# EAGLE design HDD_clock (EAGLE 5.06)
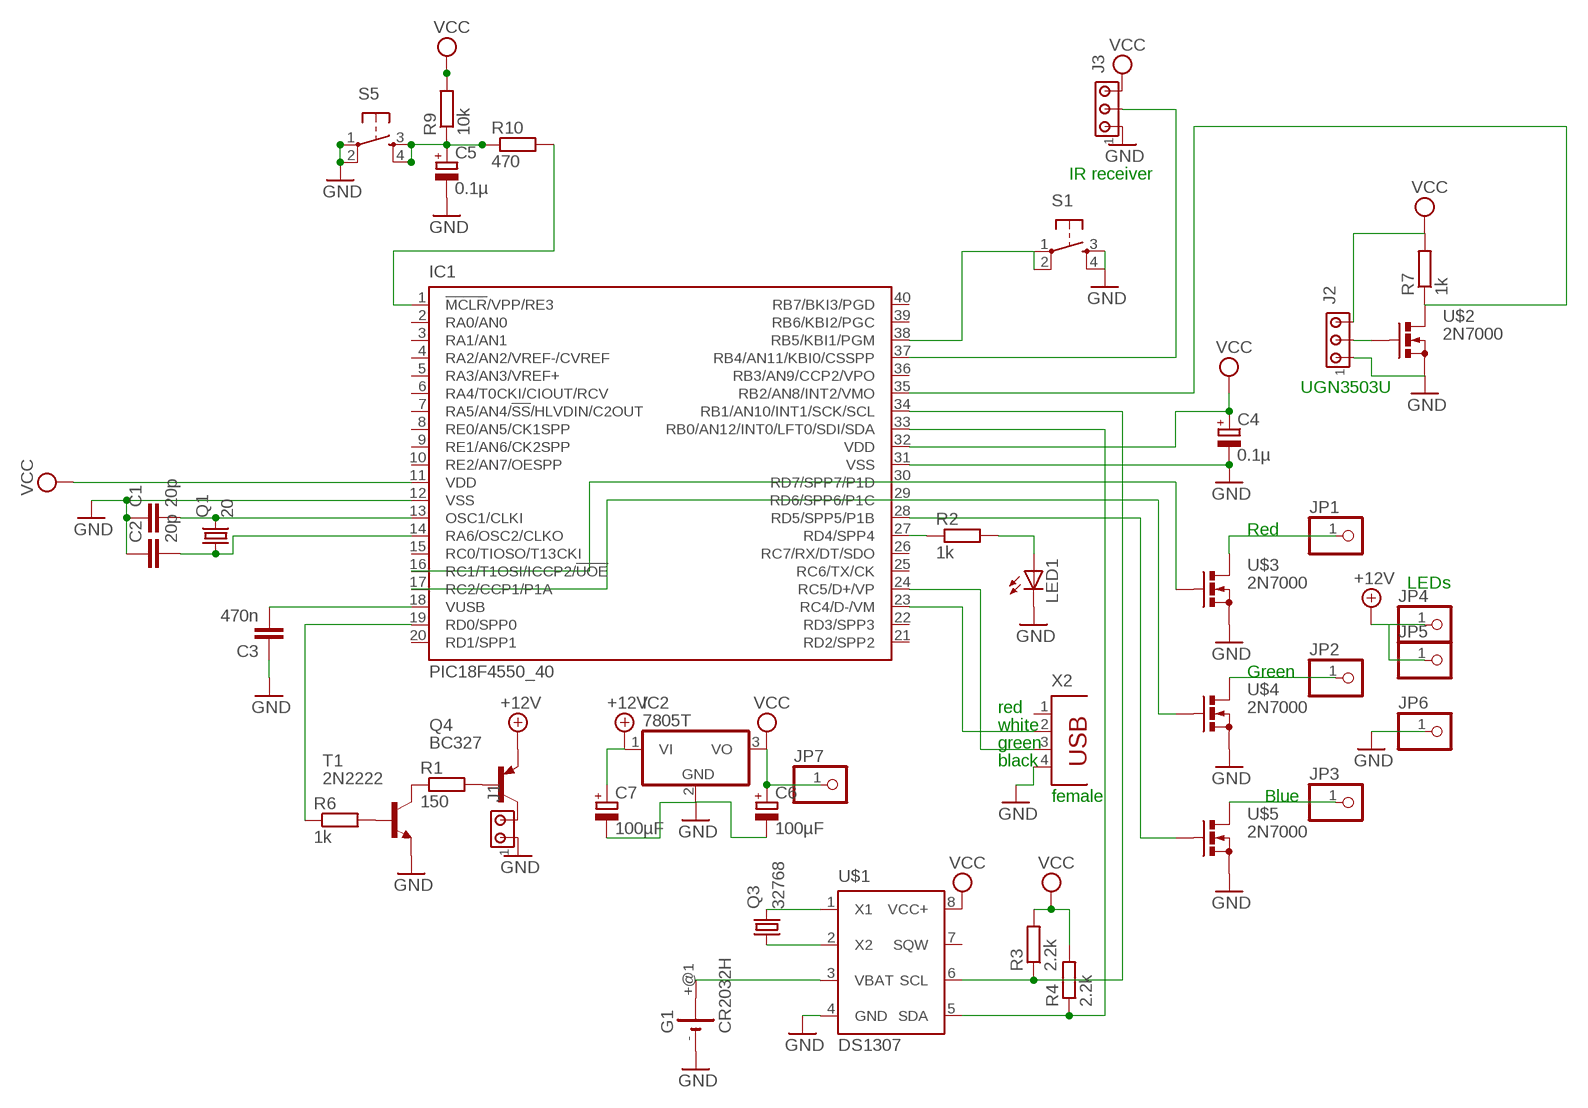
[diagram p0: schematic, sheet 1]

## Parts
C1  20p  C2.5/2  [C2.5-2]
C2  20p  C2.5/2  [C2.5-2]
C3  470n  C2.5/2  [C2.5-2]
C4  0.1µ  CPOL-EUE3.5-8  [E3,5-8]
C5  0.1µ  CPOL-EUE3.5-8  [E3,5-8]
C6  100µF  CPOL-EUTT5D7L  [TT5D7L]
C7  100µF  CPOL-EUTT5D7L  [TT5D7L]
G1  CR2032H  [CR2032H]
IC1  PIC18F4550_40  [DIL40]
IC2  7805T  [TO220H]
J1  MTA02-100  [10X02MTA]
J2  MTA03-100  [10X03MTA]
J3  MTA03-100  [10X03MTA]
JP1  PINHD-1X1  [1X01]
JP2  PINHD-1X1  [1X01]
JP3  PINHD-1X1  [1X01]
JP4  PINHD-1X1  [1X01]
JP5  PINHD-1X1  [1X01]
JP6  PINHD-1X1  [1X01]
JP7  PINHD-1X1  [1X01]
LED1  LED3MM  [LED3MM]
Q1  20  CRYSTALHC49S  [HC49/S]
Q3  32768  CRYSTALTC38H  [TC38H]
Q4  BC327  [TO92-EBC]
R1  150  R-EU_0207/15  [0207/15]
R2  1k  R-EU_0204/7  [0204/7]
R3  2.2k  R-EU_0204/7  [0204/7]
R4  2.2k  R-EU_0204/7  [0204/7]
R6  1k  R-EU_0204/7  [0204/7]
R7  1k  R-EU_0204/7  [0204/7]
R9  10k  R-EU_0204/7  [0204/7]
R10  470  R-EU_0204/7  [0204/7]
S1  TAC_SWITCHPTH  [TACTILE-PTH]
S5  TAC_SWITCHPTH  [TACTILE-PTH]
T1  2N2222  [TO18]
U$1  DS1307  [DIL8]
U$2  2N7000  [TO-92-SGD]
U$3  2N7000  [TO-92-SGD]
U$4  2N7000  [TO-92-SGD]
U$5  2N7000  [TO-92-SGD]
X2  PN87520  [PN87520]

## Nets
+12V: C7.+ IC2.1(VI) JP4.1 JP5.1 Q4.E
GND: LED1.K(C)
N$1: IC1.24(RC5/D+/VP) X2.3
N$2: C5.+ R9.1 R10.1 S5.3 S5.4
N$3: Q4.B R1.2
N$4: IC1.19(RD0/SPP0) R6.1
N$5: IC1.1(!MCLR!/VPP/RE3) R10.2
N$6: C1.2 IC1.13(OSC1/CLKI) Q1.2
N$7: C2.2 IC1.14(RA6/OSC2/CLKO) Q1.1
N$8: J1.2 Q4.C
N$9: C3.2 IC1.18(VUSB)
N$10: IC1.37(RB4/AN11/KBI0/CSSPP) J3.2
N$11: J2.2 U$2.G
N$13: C1.1 C2.1 C3.1 C4.- C5.- C6.- C7.- G1.- IC1.12(VSS) IC1.31(VSS) IC2.2(GND) J1.1 J2.1 J3.1 JP6.1 S1.3 S1.4 S5.1 S5.2 T1.1(E) U$1.4(GND) U$2.S U$3.S U$4.S U$5.S X2.4 ; supply symbol labelled GND
N$14: JP2.1 U$4.D
N$15: JP3.1 U$5.D
N$16: JP1.1 U$3.D
N$17: IC1.16(RC1/T1OSI/ICCP2/!UOE) U$3.G
N$18: IC1.17(RC2/CCP1/P1A) U$4.G
N$19: IC1.28(RD5/SPP5/P1B) U$5.G
N$20: Q3.2 U$1.1(X1)
N$21: Q3.1 U$1.2(X2)
N$22: G1.+@1(+) U$1.3(VBAT)
N$23: IC1.33(RB0/AN12/INT0/LFT0/SDI/SDA) R4.1 U$1.5(SDA)
N$24: IC1.38(RB5/KBI1/PGM) S1.1 S1.2
N$25: IC1.34(RB1/AN10/INT1/SCK/SCL) R3.1 U$1.6(SCL)
N$26: R1.1 T1.3(C)
N$27: R6.2 T1.2(B)
N$29: IC1.35(RB2/AN8/INT2/VMO) R7.1 U$2.D
N$44: IC1.27(RD4/SPP4) R2.1
N$45: LED1.A R2.2
N$70: IC1.23(RC4/D-/VM) X2.2
VCC: C4.+ C6.+ IC1.11(VDD) IC1.32(VDD) IC2.3(VO) J2.3 J3.3 JP7.1 R3.2 R4.2 R7.2 R9.2 U$1.8(VCC+)
Unconnected: G1.+ IC1.2(RA0/AN0) IC1.3(RA1/AN1) IC1.4(RA2/AN2/VREF-/CVREF) IC1.5(RA3/AN3/VREF+) IC1.6(RA4/T0CKI/CIOUT/RCV) IC1.7(RA5/AN4/!SS!/HLVDIN/C2OUT) IC1.8(RE0/AN5/CK1SPP) IC1.9(RE1/AN6/CK2SPP) IC1.10(RE2/AN7/OESPP) IC1.15(RC0/TIOSO/T13CKI) IC1.20(RD1/SPP1) IC1.21(RD2/SPP2) IC1.22(RD3/SPP3) IC1.25(RC6/TX/CK) IC1.26(RC7/RX/DT/SDO) IC1.29(RD6/SPP6/P1C) IC1.30(RD7/SPP7/P1D) IC1.36(RB3/AN9/CCP2/VPO) IC1.39(RB6/KBI2/PGC) IC1.40(RB7/BKI3/PGD) U$1.7(SQW) X2.1

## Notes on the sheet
- IR receiver
- UGN3503U
- Red
- LEDs
- Green
- red
- white
- green
- black
- female | Blue

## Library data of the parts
C1-C3 = capacitor-wima:C: CAPACITOR
C4-C7 = rcl:CPOL-EU: POLARIZED CAPACITOR, European symbol
G1 = battery:CR2032H: LI BATTERY Varta
IC1 = microchip:PIC18F4*_40: USB Microcontrollers with nanoWatt Technology High-Performance, Enhanced Flash, 28/40/44-Pin, Source: http://ww1.microchip.com/downloads/en/devicedoc/39632c.pdf
IC2 = linear:78*: Positive VOLTAGE REGULATOR Source: http://cache.national.com/ds/LM/LM78L05.pdf http://www.fairchildsemi.com/ds/LM/LM7805.pdf
J1 = con-amp:MTA02-100: AMP connector
J2 J3 = con-amp:MTA03-100: AMP connector
JP1-JP7 = pinhead:PINHD-1X1: PIN HEADER
LED1 = led:LED: LED
Q1 Q3 = crystal:CRYSTAL: CRYSTAL
Q4 = transistor-pnp:BC327*: PNP Transistror
R1-R4 R6 R7 R9 R10 = resistor:R-EU_: RESISTOR, European symbol
S1 S5 = SparkFun:TAC_SWITCH: Momentary Switch Button commonly used for reset or general input. Spark Fun Electronics SKU : COM-00097
T1 = transistor:2N2222: NPN TRANSISTOR
U$1 = JP:DS1307: DS1307 real time clock
U$2-U$5 = JP:2N7000: N channel Mosfet 2N7000
X2 = con-berg:PN87520: BERG USB connector

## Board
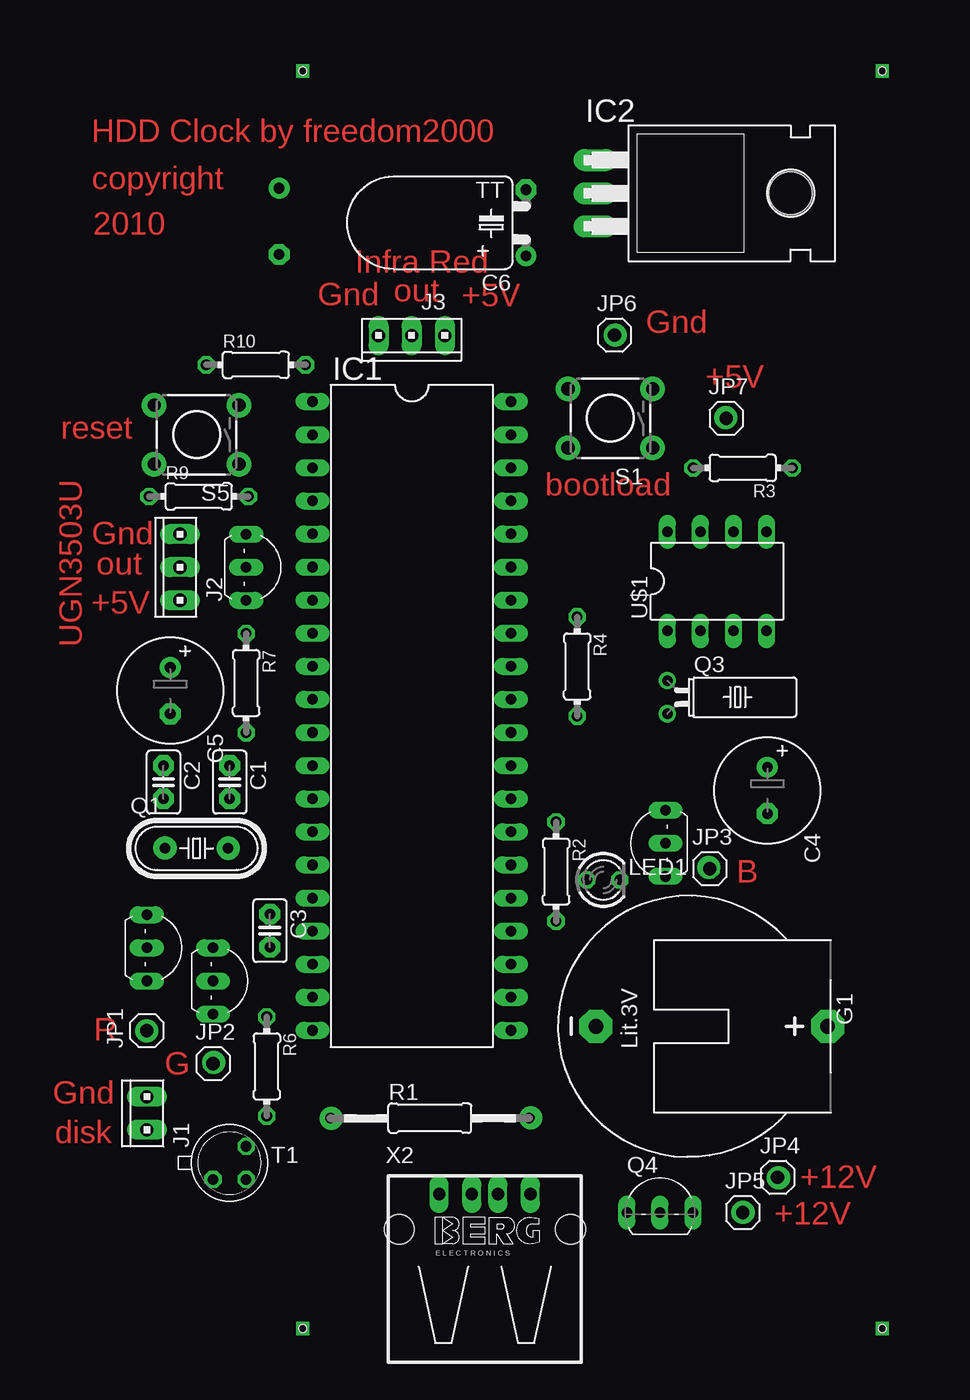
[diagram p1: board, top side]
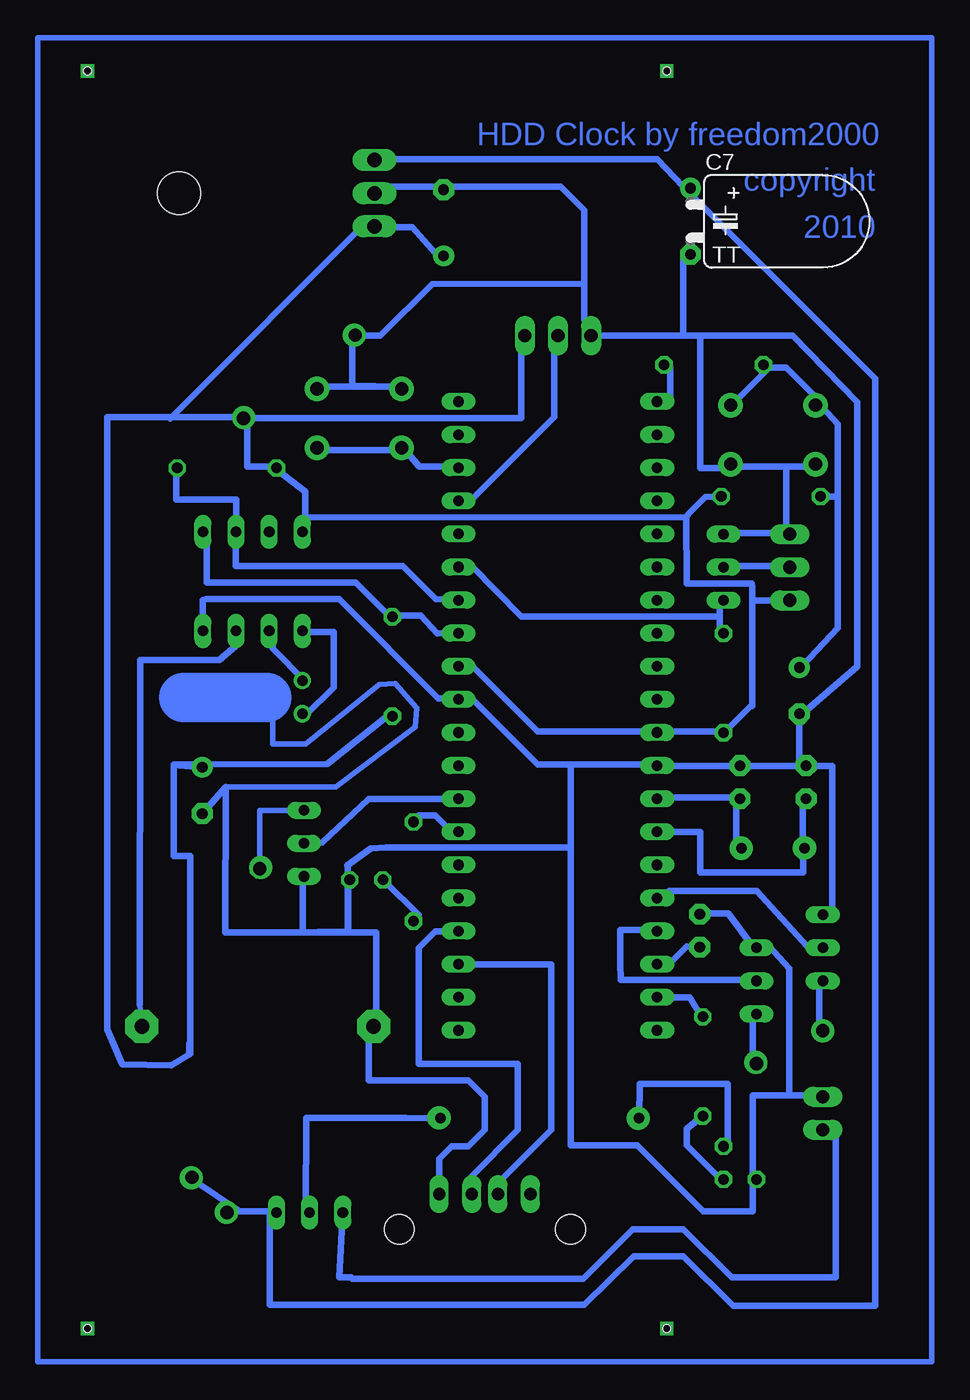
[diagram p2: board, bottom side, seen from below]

No outline drawn. Coordinates in mm, seen from the top.
Copper layers (1*16): Top 0.035mm / dielectric 1.5mm / Bottom 0.035mm
Design rules "default *": minimum track width 20mil, minimum drill 24mil, track to track 10mil, track to pad 10mil, pad to pad 10mil, via to via 10mil, smd to smd 8mil, copper to edge 40mil, drill to drill 8mil, minimum pad ring 10mil, minimum via ring 8mil, stop-mask expansion 4mil, vias tented up to drill 0mil, thermal gap 10mil
Holes 0.6 mm at 20.32,99.06 64.77,99.06 64.77,2.54 20.32,2.54

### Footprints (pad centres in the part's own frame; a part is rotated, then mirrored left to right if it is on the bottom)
C2.5-2 = drill 0.813 pad 1.6 octagon: 1 -1.27,0; 2 1.27,0
E3,5-8 = drill 0.813 pad 1.6 round: + -1.778,0 | drill 0.813 pad 1.6 octagon: - 1.778,0
TT5D7L = drill 0.813 pad 1.6 round: + -2.54,0 | drill 0.813 pad 1.6 octagon: - 2.54,0
CR2032H = drill 1.118 pad 2.54 octagon: + 0,10.795; +@1 0,10.795; - 0,-6.985
DIL40 = drill 0.813 long: 1 -24.13,-7.62; 2 -21.59,-7.62; 3 -19.05,-7.62; 4 -16.51,-7.62; 5 -13.97,-7.62; 6 -11.43,-7.62; 7 -8.89,-7.62; 8 -6.35,-7.62; 9 -3.81,-7.62; 10 -1.27,-7.62; 11 1.27,-7.62; 12 3.81,-7.62; 13 6.35,-7.62; 14 8.89,-7.62; 15 11.43,-7.62; 16 13.97,-7.62; 17 16.51,-7.62; 18 19.05,-7.62; 19 21.59,-7.62; 20 24.13,-7.62; 21 24.13,7.62; 22 21.59,7.62; 23 19.05,7.62; 24 16.51,7.62; 25 13.97,7.62; 26 11.43,7.62; 27 8.89,7.62; 28 6.35,7.62; 29 3.81,7.62; 30 1.27,7.62; 31 -1.27,7.62; 32 -3.81,7.62; 33 -6.35,7.62; 34 -8.89,7.62; 35 -11.43,7.62; 36 -13.97,7.62; 37 -16.51,7.62; 38 -19.05,7.62; 39 -21.59,7.62; 40 -24.13,7.62
TO220H = drill 1.118 long: 1 -2.54,-10.16; 2 0,-10.16; 3 2.54,-10.16 | hole 3.302: 0,4.826
10X02MTA = drill 1.016 long: 1 1.27,0; 2 -1.27,0
10X03MTA = drill 1.016 long: 1 2.54,0; 2 0,0; 3 -2.54,0
1X01 = drill 1.016 octagon: 1 0,0
LED3MM = drill 0.813 octagon: A -1.27,0; K 1.27,0
HC49/S = drill 0.813 round: 1 -2.413,0; 2 2.413,0
TC38H = drill 0.813 round: 1 -1.27,0; 2 1.27,0
TO92-EBC = drill 0.813 long: B 0,-1.27; C -2.54,-1.27; E 2.54,-1.27
0207/15 = drill 0.813 octagon: 1 -7.62,0; 2 7.62,0
0204/7 = drill 0.813 octagon: 1 -3.81,0; 2 3.81,0
TACTILE-PTH = drill 1.016 pad 1.88 round: 1 -3.251,2.261; 2 3.251,2.261; 3 -3.251,-2.261; 4 3.251,-2.261
TO18 = drill 0.813 octagon: 1 -1.27,-1.27; 2 1.27,-1.27; 3 1.27,1.27
DIL8 = drill 0.813 long: 1 -3.81,-3.81; 2 -1.27,-3.81; 3 1.27,-3.81; 4 3.81,-3.81; 5 3.81,3.81; 6 1.27,3.81; 7 -1.27,3.81; 8 -3.81,3.81
TO-92-SGD = drill 0.813 long: D 2.54,0; G 0,0; S -2.54,0
PN87520 = drill 0.95 long: 1 -3.5,2.71; 2 -1,2.71; 3 1,2.71; 4 3.5,2.71 | hole 2.3: -6.57,0; 6.57,0

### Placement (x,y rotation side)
C1  14.72,44.47 270 top
C2  9.64,44.47 270 top
C3  17.8,33.08 270 top
C4  55.97,43.84 270 top
C5  10.16,51.49 270 top
C6  37.45,87.41 90 top
C7  18.51,87.52 270 bottom
G1  49.8,25.73 270 top
IC1  28.69,49.55 270 top
IC2  52.92,89.68 270 top
J1  8.36,19.06 90 top
J2  10.9,60.97 90 top
J3  28.68,78.75 180 top
JP1  8.36,25.41 90 top
JP2  13.44,22.87 0 top
JP3  51.55,37.83 0 top
JP4  56.75,14.14 0 top
JP5  54.08,11.44 0 top
JP6  44.23,78.79 0 top
JP7  52.81,72.4 0 top
LED1  43.38,36.98 0 top
Q1  12.18,39.39 0 top
Q3  48.29,51 270 top
Q4  47.73,12.71 0 top
R1  30.07,18.69 0 top
R2  39.76,37.61 270 top
R3  54.08,68.59 180 top
R4  41.38,53.35 270 top
R6  17.56,22.66 270 top
R7  15.98,52.08 270 top
R9  12.34,66.4 0 top
R10  16.72,76.5 0 top
S1  43.92,72.4 180 top
S5  12.18,71.14 180 top
T1  14.71,15.25 0 top
U$1  52.1,59.89 0 top
U$2  15.98,60.97 270 top
U$3  8.36,31.76 270 top
U$4  13.44,29.22 270 top
U$5  48.16,39.78 90 top
X2  34.29,10.16 0 top

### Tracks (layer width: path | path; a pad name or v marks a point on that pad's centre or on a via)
+12V
  Bottom 0.508: 53.09,11.54 54.36,11.54 JP5.1 | 53.09,11.54 50.55,11.54 Q4.E 50.8,11.43 50.8,4.35 26.67,4.35 22.86,8.1 19.05,8.1 15.24,4.29 4.33,4.29 4.33,75.45 19.05,90.17 | 53.09,11.54 56.64,13.91 JP4.1 | 19.05,90.17 | 19.05,90.17 | 19.05,90.17 21.07,92.29 42.66,92.29 IC2.1 | 19.05,90.17 | 19.05,90.17 C7.+ | 19.05,90.17
N$1
  Bottom 0.406: X2.3 35.29,14.24 | 36.33,33.02 IC1.24
  Bottom 0.508: 35.29,14.24 31.75,17.78 31.75,22.86 39.37,22.86 39.37,31.75 38.1,33.02 36.33,33.02
N$2
  Bottom 0.508: 12.45,76.31 14.99,73.77 S5.3 | 12.45,76.31 R10.1 12.45,76.31 | 12.45,76.31 11.18,76.31 8.64,73.77 S5.4 8.69,73.6 8.69,73.59 7.22,71.97 7.22,66.14 7.23,66.4 | 7.23,66.4 7.23,56.31 9.91,53.45 C5.+ | 7.23,66.4 R9.1 7.23,66.4
N$3
  Bottom 0.508: Q4.B 48.01,11.54 47.97,18.71 40.35,18.71 R1.2
N$4
  Bottom 0.508: R6.1 17.69,26.51 18.57,27.95 IC1.19
N$5
  Bottom 0.508: R10.2 20.07,76.31 20.07,73.77 IC1.1
N$6
  Bottom 0.508: 14.99,43.28 14.99,39.48 Q1.2 | 14.99,43.28 C1.2 14.99,43.28 | 14.99,43.28 20.07,43.28 IC1.13
N$7
  Bottom 0.406: 9.91,39.48 9.88,39.48 | 21.07,40.64 IC1.14
  Bottom 0.508: Q1.1 9.91,39.48 9.91,43.28 C2.2 | 9.88,39.48 9.85,37.54 17.75,37.54 17.78,40.64 21.07,40.64
N$8
  Bottom 0.508: Q4.C 45.47,6.46 44.56,6.46 44.45,6.35 26.74,6.35 22.93,10.16 19.05,10.16 15.35,6.46 7.37,6.46 7.37,17.89 J1.2
N$9
  Bottom 0.508: IC1.18 20.07,30.59 18.8,31.86 C3.2
N$10
  Bottom 0.508: IC1.37 35.31,66.14 28.96,72.5 28.96,77.58 J3.2
N$11
  Bottom 0.508: U$2.G 14.99,61.07 11.18,61.07 J2.2
N$13
  Bottom 0.406: 50.55,52.17 58.17,52.17 57.37,50.98 | 50.55,52.17 51.02,50.98 | 50.55,52.17 50.55,47.42 48.01,47.42 42.38,51.96 41.15,52.05 39.51,50.16 39.64,48.69 45.72,44.1 54.15,44.1 | 13.72,13.7 T1.1 | G1.- 43.18,25.37
  Bottom 0.508: 10.93,20.43 8.64,20.43 J1.1 | 10.93,20.43 13.72,20.43 13.72,14.07 T1.1 | 17.89,34.4 C3.1 17.53,34.4 15.61,34.4 13.72,31.86 U$4.S 12.45,31.86 10.93,30.19 10.93,20.43 | C4.- 55.51,42.59 54.15,44.1 54.2,32.93 49.53,32.93 | 42.64,32.93 42.64,26.97 42.93,26.78 G1.- | 42.64,32.93 44.78,32.94 44.78,36.99 | 48.26,32.93 42.64,32.93 | 49.53,32.93 48.26,32.93 | 27.69,39.48 27.69,45.83 | 27.69,45.83 21.34,45.83 IC1.12 20.32,45.72 15.24,45.72 C1.1 13.97,45.72 10.16,45.72 | 27.69,39.48 41.66,39.48 41.85,39.46 43.06,39.4 44.84,38.1 44.8,38.1 44.8,33.02 49.53,32.93 | 27.69,39.48 27.69,16.62 27.63,16.62 22.61,16.62 21.34,15.35 17.53,11.54 13.72,11.54 13.72,13.7 | 27.69,45.83 30.23,45.83 31.5,47.1 35.31,50.91 IC1.31 36.58,50.91 37.85,50.91 45.47,58.53 55.62,58.53 55.93,58.46 U$1.4 | 11.18,63.6 14.99,63.6 U$2.S | 11.18,63.6 J2.1 11.18,63.6 | 11.18,68.69 14.99,68.69 S5.1 15.24,68.58 17.78,68.58 17.78,71.12 17.78,78.74 | 11.18,68.69 8.64,68.69 S5.2 | 11.18,68.69 11.18,63.6 | U$3.S 7.62,34.29 7.62,45.72 8.89,45.72 C2.1 | 10.16,45.72 10.16,49.53 | 10.16,49.53 C5.- 10.16,49.53 | 10.16,45.72 C2.1 | 10.16,45.72 C2.1 | 44.47,74.91 41.09,74.8 S1.4 | 44.45,78.74 44.47,74.91 | 44.45,78.74 JP6.1 44.45,78.74 | 44.47,74.91 40.84,74.85 46.92,74.83 S1.3 | 26.67,82.72 26.67,88.38 28.46,90.17 36.83,90.17 38.1,90.17 | 26.67,82.72 26.67,80.01 J3.1 | 38.1,90.17 43.18,90.17 IC2.2 | 26.67,82.72 38.33,82.71 42.3,78.74 44.45,78.74 | 17.78,78.74 19.05,78.74 | 19.05,78.74 25.4,78.74 | 25.4,78.74 J3.1 | 10.16,49.53 5.73,53.34 5.73,73.66 10.68,78.74 17.78,78.74 | 17.78,78.74 19.05,78.74 | 19.05,78.74 25.4,78.74 | 25.4,78.74 J3.1 | 38.1,90.17 C6.-
  Bottom 0.508: 19.05,78.74 19.05,85.09 C7.- | U$5.S 48.26,36.83 48.26,33.02 48.26,32.93 | X2.4 37.79,15.55 36.83,16.51 35.56,16.51 34.29,17.78 34.29,20.32 35.56,21.59 43.18,21.59 43.18,25.37
  Bottom 3.81: 51.02,50.98 57.37,50.98
N$14
  Bottom 0.508: U$4.D 13.72,26.78 13.72,22.96 JP2.1
N$15
  Bottom 0.406: U$5.D 51.55,42.32 JP3.1
N$16
  Bottom 0.508: U$3.D 8.64,29.32 8.64,25.51 JP1.1
N$17
  Bottom 0.508: U$3.G 9.55,31.86 13.41,36.11 20.12,36.11 IC1.16
N$18
  Bottom 0.508: U$4.G 13.72,29.32 23.87,29.32 23.88,30.59 23.88,33.13 21.34,33.13 IC1.17
N$19
  Bottom 0.508: IC1.28 36.83,43.18 43.18,43.18 46.75,39.85 U$5.G
N$20
  Bottom 0.508: Q3.2 48.01,49.64 45.89,51.75 45.89,55.99 48.01,55.99 U$1.1
N$21
  Bottom 0.508: Q3.1 48.01,52.17 50.55,54.72 50.55,55.99 U$1.2
N$22
  Bottom 0.406: U$1.3 53.37,55 53.38,54.91 | G1.+@1 60.76,27.41
  Bottom 0.508: 53.38,54.91 54.65,53.85 60.73,53.85 60.76,27.41
N$23
  Bottom 0.508: 41.66,57.26 39.21,57.26 37.94,55.88 IC1.33 | 41.66,57.26 R4.1 41.66,57.26 | 41.66,57.26 44.2,59.8 55.63,59.8 55.63,63.6 U$1.5
N$24
  Bottom 0.508: 40.39,69.96 39.31,68.7 36.58,68.69 IC1.38 | 40.39,69.96 S1.2 40.39,69.96 | 40.39,69.96 46.74,69.96 S1.1
N$25
  Bottom 0.508: IC1.34 38.05,58.53 40.59,61.07 53.41,61.07 53.39,63.6 U$1.6 53.35,66.14 57.96,66.14 57.96,68.69 R3.1
N$26
  Bottom 0.508: T1.3 15.66,16.62 15.66,21.32 22.39,21.32 R1.1
N$27
  Bottom 0.508: T1.2 16.26,14.07 18.8,16.62 18.8,17.89 R6.2
N$28  (via drill 0.6 pad 1.78)
  other vias: 22.51,18.67
N$29
  Bottom 0.508: 16.26,57.18 16.26,58.53 U$2.D | 16.26,57.18 16.26,55.99 R7.1 | 16.26,57.18 31.5,57.18 35.31,61.07 IC1.35
N$30  (via drill 0.6)
  other vias: 20.32,99.06
N$31  (via drill 0.6)
  other vias: 64.77,99.06
N$32  (via drill 0.6)
  other vias: 64.77,2.54
N$33  (via drill 0.6)
  other vias: 20.32,2.54
N$34  (via drill 0.6 pad 1.78)
  other vias: 37.81,18.7
N$35  (via drill 0.6 pad 1.78)
  other vias: 13.5,22.98
N$36  (via drill 0.6 pad 1.78)
  other vias: 56.82,14.11
N$37  (via drill 0.6 pad 1.78)
  other vias: 54.1,11.47
N$38  (via drill 0.6 pad 1.78)
  other vias: 8.36,25.37
N$39  (via drill 0.6 pad 1.78)
  other vias: 44.3,78.79
N$40  (via drill 0.6 pad 1.78)
  other vias: 52.78,72.44
N$41  (via drill 0.6 pad 1.78)
  other vias: 51.48,37.93
N$42  (via drill 0.6 pad 1.78)
  other vias: 9.76,39.42
N$43  (via drill 0.6 pad 1.78)
  other vias: 14.61,39.4
N$44
  Bottom 0.508: IC1.27 36.83,40.64 38.1,41.91 39.37,41.91 R2.1
N$45
  Bottom 0.508: R2.2 39.37,34.29 41.91,36.83 LED1.A
N$46
  Bottom 0.406: 0,0 68.58,0 68.58,101.6 0,101.6 0,0
N$70
  Bottom 0.406: X2.2 33.29,13.7 | 36.28,30.48 IC1.23
  Bottom 0.508: 33.29,13.7 29.21,17.78 29.21,30.48 36.28,30.48
VCC
  Bottom 0.508: 16.26,48.37 20.07,48.37 IC1.11 21.34,48.37 30.23,48.37 | 16.26,48.37 R7.2 | 58.17,45.79 58.17,45.83 46.36,45.86 41.66,49.64 R4.2 | 58.17,45.79 C4.+ | 56.95,23.74 56.95,24.42 56.87,23.89 56.9,24.23 | 56.9,24.23 56.9,38.82 | 56.9,38.82 58.17,38.81 | 58.17,38.81 58.17,45.79 | 58.17,45.79 C4.+ | 30.23,48.37 35.31,53.45 IC1.32 | 13.78,58.41 13.77,50.33 13.77,50.45 15.86,48.37 16.26,48.37 | 16.26,48.37 30.23,48.37 | 13.78,58.41 J2.3 13.78,58.41 | 48.07,64.78 48.06,66.77 50.55,68.69 | 48.07,64.78 U$1.8 48.07,64.78 | 50.55,68.69 R3.2 50.55,68.69 | 18.83,64.82 48.07,64.78 | 18.83,64.82 18.64,65.08 17.37,66.35 R9.2 | 52.5,72.41 52.5,68.69 50.55,68.69 | 52.5,72.41 53.09,72.5 | 53.09,72.5 JP7.1 53.09,72.5 | 52.5,72.41 53.09,72.5 | 52.5,72.41 53.77,72.5 | 52.5,72.41 53.09,72.5 | 52.5,72.41 53.09,72.5 | 52.5,72.41 31.5,72.41 31.5,77.58 J3.3 | 13.78,58.41 13.78,58.53 13.79,59.5 13.79,59.73 14.25,59.73 18.8,59.72 18.83,64.82 | 58.17,38.81 58.17,45.79 | 56.9,38.82 58.17,38.81 | 56.9,24.23 56.9,38.82 | 56.9,24.23 56.9,23.75 56.91,23.61 58.36,22.73 62.09,22.8 63.25,25.51 63.25,72.5 58.42,72.5 | 53.77,72.5 58.42,72.5 | 52.5,72.41 53.77,72.5 | 58.17,45.79 C4.+ | 58.42,72.5 58.42,72.39 43.18,87.63 IC2.3 42.06,87.06 39.87,87.06 38.1,85.09 C6.+

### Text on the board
Top: HDD Clock by freedom2000 | copyright | 2010 | Infra Red | Gnd | out | +5V | Gnd | +5V | reset | bootload | Gnd | out | +5V | UGN3503U | B | R | G | Gnd | disk | +12V | +12V
Bottom: HDD Clock by freedom2000 | copyright | 2010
